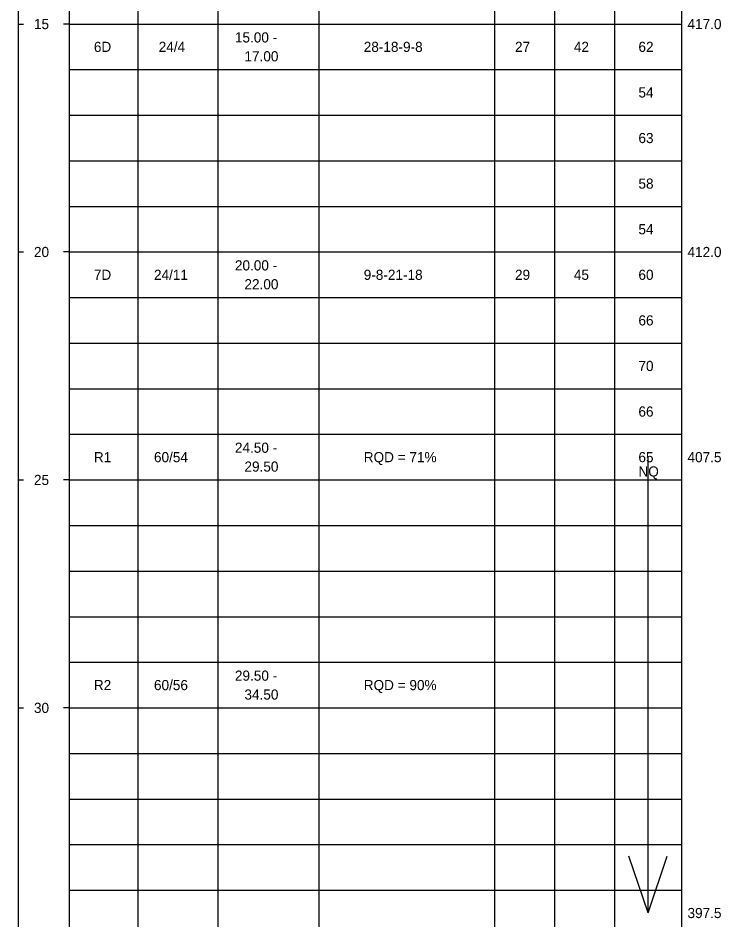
# Model space of a CAD drawing. Extents: x 9419 to 9552, y 6780 to 6865.
# Drawn here: x 9422.45 to 9437.86, y 6812.36 to 6832.14 of the extents above; entities that cross this region are included whole.
import ezdxf

# ---------------------------------------------------------------- set-up
doc = ezdxf.new("R2010")
doc.units = 0
doc.layers.add('7', color=7, linetype='Continuous')

msp = doc.modelspace()

# ---------------------------------------------------------------- linework, layer by layer
at = {"layer": '7'}
for p, q in [((9436.264, 6822.011), (9436.264, 6822.511)), ((9436.264, 6812.511), (9436.264, 6822.011)), ((9436.264, 6812.511), (9435.847, 6813.761)), ((9436.264, 6812.511), (9436.681, 6813.761))]:
    msp.add_line(p, q, dxfattribs=at)
for points in [[(9422.449, 6860.114), (9422.449, 6821.983)], [(9423.567, 6850.528), (9423.567, 6821.983)], [(9425.076, 6849.992), (9425.076, 6821.983)], [(9426.831, 6849.992), (9426.831, 6821.983)], [(9429.046, 6849.992), (9429.046, 6821.983)], [(9432.901, 6849.992), (9432.901, 6821.983)], [(9434.213, 6849.992), (9434.213, 6821.983)], [(9435.526, 6849.992), (9435.526, 6821.983)], [(9437.002, 6849.992), (9437.002, 6821.983)], [(9422.449, 6832.011), (9422.571, 6832.011)], [(9423.567, 6832.011), (9423.445, 6832.011)], [(9423.567, 6832.011), (9425.076, 6832.011)], [(9425.076, 6832.011), (9426.831, 6832.011)], [(9426.831, 6832.011), (9429.046, 6832.011)], [(9429.046, 6832.011), (9432.901, 6832.011)], [(9432.901, 6832.011), (9434.213, 6832.011)], [(9434.213, 6832.011), (9435.526, 6832.011)], [(9435.526, 6832.011), (9437.002, 6832.011)], [(9423.567, 6831.011), (9425.076, 6831.011)], [(9425.076, 6831.011), (9426.831, 6831.011)], [(9426.831, 6831.011), (9429.046, 6831.011)], [(9429.046, 6831.011), (9432.901, 6831.011)], [(9432.901, 6831.011), (9434.213, 6831.011)], [(9434.213, 6831.011), (9435.526, 6831.011)], [(9435.526, 6831.011), (9437.002, 6831.011)], [(9423.567, 6830.011), (9425.076, 6830.011)], [(9425.076, 6830.011), (9426.831, 6830.011)], [(9426.831, 6830.011), (9429.046, 6830.011)], [(9429.046, 6830.011), (9432.901, 6830.011)], [(9432.901, 6830.011), (9434.213, 6830.011)], [(9434.213, 6830.011), (9435.526, 6830.011)], [(9435.526, 6830.011), (9437.002, 6830.011)], [(9423.567, 6829.011), (9425.076, 6829.011)], [(9425.076, 6829.011), (9426.831, 6829.011)], [(9426.831, 6829.011), (9429.046, 6829.011)], [(9429.046, 6829.011), (9432.901, 6829.011)], [(9432.901, 6829.011), (9434.213, 6829.011)], [(9434.213, 6829.011), (9435.526, 6829.011)], [(9435.526, 6829.011), (9437.002, 6829.011)], [(9423.567, 6828.011), (9425.076, 6828.011)], [(9425.076, 6828.011), (9426.831, 6828.011)], [(9426.831, 6828.011), (9429.046, 6828.011)], [(9429.046, 6828.011), (9432.901, 6828.011)], [(9432.901, 6828.011), (9434.213, 6828.011)], [(9434.213, 6828.011), (9435.526, 6828.011)], [(9435.526, 6828.011), (9437.002, 6828.011)], [(9422.449, 6827.011), (9422.571, 6827.011)], [(9423.567, 6827.011), (9423.445, 6827.011)], [(9423.567, 6827.011), (9425.076, 6827.011)], [(9425.076, 6827.011), (9426.831, 6827.011)], [(9426.831, 6827.011), (9429.046, 6827.011)], [(9429.046, 6827.011), (9432.901, 6827.011)], [(9432.901, 6827.011), (9434.213, 6827.011)], [(9434.213, 6827.011), (9435.526, 6827.011)], [(9435.526, 6827.011), (9437.002, 6827.011)], [(9423.567, 6826.011), (9425.076, 6826.011)], [(9425.076, 6826.011), (9426.831, 6826.011)], [(9426.831, 6826.011), (9429.046, 6826.011)], [(9429.046, 6826.011), (9432.901, 6826.011)], [(9432.901, 6826.011), (9434.213, 6826.011)], [(9434.213, 6826.011), (9435.526, 6826.011)], [(9435.526, 6826.011), (9437.002, 6826.011)], [(9423.567, 6825.011), (9425.076, 6825.011)], [(9425.076, 6825.011), (9426.831, 6825.011)], [(9426.831, 6825.011), (9429.046, 6825.011)], [(9429.046, 6825.011), (9432.901, 6825.011)], [(9432.901, 6825.011), (9434.213, 6825.011)], [(9434.213, 6825.011), (9435.526, 6825.011)], [(9435.526, 6825.011), (9437.002, 6825.011)], [(9423.567, 6824.011), (9425.076, 6824.011)], [(9425.076, 6824.011), (9426.831, 6824.011)], [(9426.831, 6824.011), (9429.046, 6824.011)], [(9429.046, 6824.011), (9432.901, 6824.011)], [(9432.901, 6824.011), (9434.213, 6824.011)], [(9434.213, 6824.011), (9435.526, 6824.011)], [(9435.526, 6824.011), (9437.002, 6824.011)], [(9423.567, 6823.011), (9425.076, 6823.011)], [(9425.076, 6823.011), (9426.831, 6823.011)], [(9426.831, 6823.011), (9429.046, 6823.011)], [(9429.046, 6823.011), (9432.901, 6823.011)], [(9432.901, 6823.011), (9434.213, 6823.011)], [(9434.213, 6823.011), (9435.526, 6823.011)], [(9435.526, 6823.011), (9437.002, 6823.011)], [(9422.449, 6822.038), (9422.449, 6791.992)], [(9422.449, 6822.011), (9422.571, 6822.011)], [(9422.449, 6822.011), (9422.571, 6822.011)], [(9423.567, 6822.011), (9423.445, 6822.011)], [(9423.567, 6822.011), (9423.445, 6822.011)], [(9423.567, 6822.038), (9423.567, 6796.983)], [(9423.567, 6822.011), (9425.076, 6822.011)], [(9425.076, 6822.038), (9425.076, 6796.983)], [(9425.076, 6822.011), (9426.831, 6822.011)], [(9426.831, 6822.038), (9426.831, 6796.983)], [(9426.831, 6822.011), (9429.046, 6822.011)], [(9429.046, 6822.038), (9429.046, 6796.983)], [(9429.046, 6822.011), (9432.901, 6822.011)], [(9432.901, 6822.038), (9432.901, 6796.983)], [(9432.901, 6822.011), (9434.213, 6822.011)], [(9434.213, 6822.038), (9434.213, 6796.983)], [(9434.213, 6822.011), (9435.526, 6822.011)], [(9435.526, 6822.038), (9435.526, 6796.983)], [(9435.526, 6822.011), (9437.002, 6822.011)], [(9437.002, 6822.038), (9437.002, 6796.983)], [(9423.567, 6821.011), (9425.076, 6821.011)], [(9425.076, 6821.011), (9426.831, 6821.011)], [(9426.831, 6821.011), (9429.046, 6821.011)], [(9429.046, 6821.011), (9432.901, 6821.011)], [(9432.901, 6821.011), (9434.213, 6821.011)], [(9434.213, 6821.011), (9435.526, 6821.011)], [(9435.526, 6821.011), (9437.002, 6821.011)], [(9423.567, 6820.011), (9425.076, 6820.011)], [(9425.076, 6820.011), (9426.831, 6820.011)], [(9426.831, 6820.011), (9429.046, 6820.011)], [(9429.046, 6820.011), (9432.901, 6820.011)], [(9432.901, 6820.011), (9434.213, 6820.011)], [(9434.213, 6820.011), (9435.526, 6820.011)], [(9435.526, 6820.011), (9437.002, 6820.011)], [(9423.567, 6819.011), (9425.076, 6819.011)], [(9425.076, 6819.011), (9426.831, 6819.011)], [(9426.831, 6819.011), (9429.046, 6819.011)], [(9429.046, 6819.011), (9432.901, 6819.011)], [(9432.901, 6819.011), (9434.213, 6819.011)], [(9434.213, 6819.011), (9435.526, 6819.011)], [(9435.526, 6819.011), (9437.002, 6819.011)], [(9423.567, 6818.011), (9425.076, 6818.011)], [(9425.076, 6818.011), (9426.831, 6818.011)], [(9426.831, 6818.011), (9429.046, 6818.011)], [(9429.046, 6818.011), (9432.901, 6818.011)], [(9432.901, 6818.011), (9434.213, 6818.011)], [(9434.213, 6818.011), (9435.526, 6818.011)], [(9435.526, 6818.011), (9437.002, 6818.011)], [(9422.449, 6817.011), (9422.571, 6817.011)], [(9423.567, 6817.011), (9423.445, 6817.011)], [(9423.567, 6817.011), (9425.076, 6817.011)], [(9425.076, 6817.011), (9426.831, 6817.011)], [(9426.831, 6817.011), (9429.046, 6817.011)], [(9429.046, 6817.011), (9432.901, 6817.011)], [(9432.901, 6817.011), (9434.213, 6817.011)], [(9434.213, 6817.011), (9435.526, 6817.011)], [(9435.526, 6817.011), (9437.002, 6817.011)], [(9423.567, 6816.011), (9425.076, 6816.011)], [(9425.076, 6816.011), (9426.831, 6816.011)], [(9426.831, 6816.011), (9429.046, 6816.011)], [(9429.046, 6816.011), (9432.901, 6816.011)], [(9432.901, 6816.011), (9434.213, 6816.011)], [(9434.213, 6816.011), (9435.526, 6816.011)], [(9435.526, 6816.011), (9437.002, 6816.011)], [(9423.567, 6815.011), (9425.076, 6815.011)], [(9425.076, 6815.011), (9426.831, 6815.011)], [(9426.831, 6815.011), (9429.046, 6815.011)], [(9429.046, 6815.011), (9432.901, 6815.011)], [(9432.901, 6815.011), (9434.213, 6815.011)], [(9434.213, 6815.011), (9435.526, 6815.011)], [(9435.526, 6815.011), (9437.002, 6815.011)], [(9423.567, 6814.011), (9425.076, 6814.011)], [(9425.076, 6814.011), (9426.831, 6814.011)], [(9426.831, 6814.011), (9429.046, 6814.011)], [(9429.046, 6814.011), (9432.901, 6814.011)], [(9432.901, 6814.011), (9434.213, 6814.011)], [(9434.213, 6814.011), (9435.526, 6814.011)], [(9435.526, 6814.011), (9437.002, 6814.011)], [(9423.567, 6813.011), (9425.076, 6813.011)], [(9425.076, 6813.011), (9426.831, 6813.011)], [(9426.831, 6813.011), (9429.046, 6813.011)], [(9429.046, 6813.011), (9432.901, 6813.011)], [(9432.901, 6813.011), (9434.213, 6813.011)], [(9434.213, 6813.011), (9435.526, 6813.011)], [(9435.526, 6813.011), (9437.002, 6813.011)]]:
    msp.add_lwpolyline(points, dxfattribs=at)

# ---------------------------------------------------------------- texts
for s, p in [('15', (9422.798, 6831.899)), ('417.0', (9437.13, 6831.899)), ('15.00 -', (9427.205, 6831.606)), ('6D', (9424.112, 6831.399)), ('24/4', (9425.534, 6831.399)), ('28-18-9-8', (9430.03, 6831.399)), ('27', (9433.347, 6831.399)), (' 42', (9434.555, 6831.399)), ('62', (9436.054, 6831.399)), ('17.00', (9427.414, 6831.192)), ('54', (9436.054, 6830.399)), ('63', (9436.054, 6829.399)), ('58', (9436.054, 6828.399)), ('54', (9436.054, 6827.399)), ('20', (9422.798, 6826.899)), ('412.0', (9437.13, 6826.899)), ('20.00 -', (9427.205, 6826.606)), ('7D', (9424.112, 6826.399)), ('24/11', (9425.43, 6826.399)), ('9-8-21-18', (9430.03, 6826.399)), ('29', (9433.347, 6826.399)), (' 45', (9434.555, 6826.399)), ('60', (9436.054, 6826.399)), ('22.00', (9427.414, 6826.192)), ('66', (9436.054, 6825.399)), ('70', (9436.054, 6824.399)), ('66', (9436.054, 6823.399)), ('24.50 -', (9427.205, 6822.606)), ('R1', (9424.112, 6822.399)), ('60/54', (9425.43, 6822.399)), ('RQD = 71%%%', (9430.03, 6822.399)), ('65', (9436.054, 6822.399)), ('407.5', (9437.13, 6822.399)), ('29.50', (9427.414, 6822.192)), ('NQ', (9436.054, 6822.085)), ('25', (9422.798, 6821.899)), ('29.50 -', (9427.205, 6817.606)), ('R2', (9424.112, 6817.399)), ('60/56', (9425.43, 6817.399)), ('RQD = 90%%%', (9430.03, 6817.399)), ('34.50', (9427.414, 6817.192)), ('30', (9422.798, 6816.899)), ('397.5', (9437.13, 6812.399))]:
    msp.add_text(s, height=0.2228, dxfattribs=at).set_placement(p)

doc.saveas('drawing.dxf')
